(* Logix 5000 project; controller WuXi vendor 1 type 14 code 77 rev 20.12; software revision ? *)

TASK MainTask (continuous, watchdog 500 ms) : MainProgram

MODULES
   Controller : vendor 1 type 14 code 77 (CompactLogixL32EController 0, rev 20.12)
      LocalENB : 1769-L32E Ethernet Port (CompactLogixL32Ethernet 1, rev 20.11)
         inverter1 : vendor 1471 type 12 code 200 (Ethernet 192.168.1.205, rev 1.2, StandardDataDriven RPI 30 ms)
              inverter1:O.DATA[5]   // smart drive减速时间
              inverter1:O.DATA[0]   // smart drive输出控制字节
              inverter1:O.DATA[3]   // smart drive加速时间
              inverter1:O.DATA[1]   // smart drive频率
         inverter2 : vendor 1471 type 12 code 200 (Ethernet 192.168.1.206, rev 1.2, StandardDataDriven RPI 30 ms)
      Local : CompactBus (CompactVirtualAdapter 3, rev 20.11)
END_MODULES

TYPE SD_Control :   // Smart drive 控制数据
STRUCT
   MotorFW : BOOL;   // 电机正传
   MotorRVS : BOOL;   // 电机反转
   Reset : BOOL;   // 系统复位
   Output1 : BOOL;   // 输出1
   Output2 : BOOL;   // 输出2
   Output3 : BOOL;   // 输出3
   Output4 : BOOL;   // 输出4
   LocalEnable : BOOL;   // 转速,停止由smart drive内部控制
   Speed : INT;   // 运行速度 10000对应50HZ
   AccelerTime : INT;   // 加速时间
   DecelerTime : INT;   // 减速时间
END_STRUCT
END_TYPE

TYPE SD_State :   // smart drive状态数据
STRUCT
   Trip : BOOL;   // Trip bit位：0：正常，1：故障，触发条件是通过380V的开关进行触发产生
   WarningPresent : BOOL;   // Reserved
   RunningFWD : BOOL;   // 电机正向运行
   RunningRVS : BOOL;   // 电机反向运行
   Ready : BOOL;   // Ready bit位：0：故障，1：正常，触发条件系统各个子系统有异常就触发
   NetCtrlStat : BOOL;   // Reserved
   NetRefStats : BOOL;   // Reserved
   CurntFlow : BOOL;   // Reserved
   ReservedBit8 : BOOL;   // Reserved
   ReservedBit9 : BOOL;   // Reserved
   ReservedBit10 : BOOL;   // Reserved
   ReservedBit11 : BOOL;   // Reserved
   KeyPadOn : BOOL;   // Keypad On
   DiscOn : BOOL;   // Disconnecter On, 正常状态为ON(=1) 380V bit0相反
   ReservedBit14 : BOOL;   // Reserved
   ReservedBit15 : BOOL;   // Reserved
   ShortCircuit : BOOL;   // 短路
   OverLoad : BOOL;   // 过载
   PhaseLoss : BOOL;   // 缺相
   ReservedBit19 : BOOL;   // Reserved
   ReservedBit20 : BOOL;   // Reserved
   ControlPowerLost : BOOL;   // 控制电丢失
   ComFault : BOOL;   // 通讯错误
   ReservedBit23 : BOOL;   // Reserved
   PhaseImbalance : BOOL;   // 相位失衡
   ReservedBit25 : BOOL;   // Reserved
   ReservedBit26 : BOOL;   // Reserved
   ReservedBit27 : BOOL;   // Reserved
   ReservedBit28 : BOOL;   // Reserved
   HardwareFault : BOOL;   // 硬件故障
   ReservedBit30 : BOOL;   // Reserved
   ReservedBit31 : BOOL;   // Reserved
   Current : INT;   // 电流整数，需乘以0.01
   Input1 : BOOL;   // 输入1
   Input2 : BOOL;   // 输入2
   Input3 : BOOL;   // 输入3
   Input4 : BOOL;   // 输入4
   Input5 : BOOL;   // 输入5
   Input6 : BOOL;   // 输入6
   Input7 : BOOL;   // 输入7
   Input8 : BOOL;   // 输入8
END_STRUCT
END_TYPE

VAR_GLOBAL   (* controller tags *)
   ControlData1 : SD_Control;
   ControlData2 : SD_Control;
   CtlcycTest : BOOL;
   CtlForward1 : BOOL;   // 正传
   CtlForward2 : BOOL;
   CtlReset : BOOL;   // 复位
   CtlReverse1 : BOOL;   // 反转
   CtlReverse2 : BOOL;
   CtlStepTest : BOOL;   // 流程测试
   CtlStop : BOOL;
   CtlStop1 : BOOL;   // 停止
   CtlStop2 : BOOL;
   inverter1input1 : ALIAS FOR StateData1.Input1;
   inverter1input4 : ALIAS FOR StateData1.Input4;
   inverter2input1 : ALIAS FOR StateData2.Input1;
   inverter2input4 : ALIAS FOR StateData2.Input4;
   Left : BOOL;
   q11 : ALIAS FOR ControlData1.MotorFW;
   q12 : ALIAS FOR ControlData1.MotorRVS;
   q21 : ALIAS FOR ControlData2.MotorFW;
   q22 : ALIAS FOR ControlData2.MotorRVS;
   Right : BOOL;
   StateData1 : SD_State;
   StateData2 : SD_State;
END_VAR

PROGRAM MainProgram   (* main routine MainRoutine *)
VAR
   Action_000 : SFC_ACTION := (Status := 16#0020_0000, PauseTimer := 1);
   Action_001 : SFC_ACTION := (Status := 16#0020_0000, PauseTimer := 1, PRE := 2000);
   Action_002 : SFC_ACTION := (Status := 16#0020_0000, PauseTimer := 1);
   Action_003 : SFC_ACTION := (Status := 16#0020_0000, PauseTimer := 1, PRE := 2000);
   Step_000 : SFC_STEP := (Status := 16#0020_0000, PauseTimer := 1);
   Step_001 : SFC_STEP := (Status := 16#0020_0000, PauseTimer := 1);
   Step_002 : SFC_STEP := (Status := 16#0020_0000, PauseTimer := 1);
   Step_003 : SFC_STEP := (Status := 16#0020_0000, PauseTimer := 1);
   temp0 : BOOL;
   temp01 : BOOL;
   temp010 : BOOL;
   temp011 : BOOL;
   temp012 : BOOL;
   temp013 : BOOL;
   temp014 : BOOL;
   temp015 : BOOL;
   temp016 : BOOL;
   temp017 : BOOL;
   temp018 : BOOL;
   temp019 : BOOL;
   temp02 : BOOL;
   temp020 : BOOL;
   temp03 : BOOL;
   temp04 : BOOL;
   temp05 : BOOL;
   temp06 : BOOL;
   temp07 : BOOL;
   temp08 : BOOL;
   temp09 : BOOL;
   time0 : TIMER := (PRE := 70);   // 复位时间需保持>50ms
   time1 : TIMER;
   Tran_000 : BOOL;
   Tran_001 : BOOL;
   Tran_002 : BOOL;
   Tran_003 : BOOL;
END_VAR

ROUTINE cycTest   (* sequential function chart *)
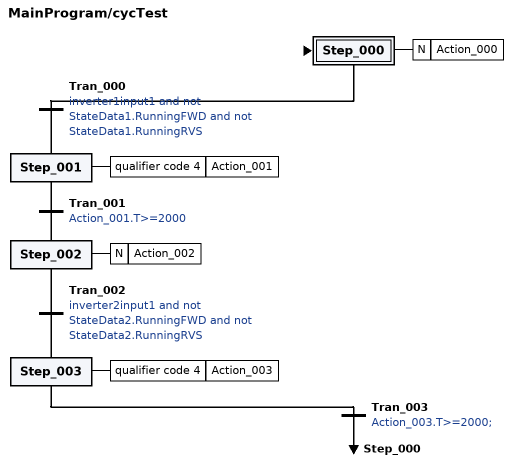
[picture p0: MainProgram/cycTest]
   INITIAL_STEP Step_000:
      ACTION Action_000 (N):
         Left:=1;
         
         
      END_ACTION
   END_STEP
   TRANSITION Tran_000 FROM Step_000 TO Step_001
      := inverter1input1 and not StateData1.RunningFWD and not StateData1.RunningRVS
         
   END_TRANSITION
   STEP Step_001:
      ACTION Action_001 (qualifier code 4):
         Left:=0;
      END_ACTION
   END_STEP
   TRANSITION Tran_001 FROM Step_001 TO Step_002
      := Action_001.T>=2000
   END_TRANSITION
   STEP Step_002:
      ACTION Action_002 (N):
         Right:=1;
      END_ACTION
   END_STEP
   TRANSITION Tran_002 FROM Step_002 TO Step_003
      := inverter2input1 and not StateData2.RunningFWD and not StateData2.RunningRVS
   END_TRANSITION
   STEP Step_003:
      ACTION Action_003 (qualifier code 4):
         Right:=0;
      END_ACTION
   END_STEP
   TRANSITION Tran_003 FROM Step_003 TO Step_000
      := Action_003.T>=2000;
         
   END_TRANSITION
END_ROUTINE

ROUTINE endcyc   (* structured text *)
   SFR(cycTest, Step_000);
   Left:=0;
   Right:=0;
   
END_ROUTINE

ROUTINE MainRoutine   (* ladder *)
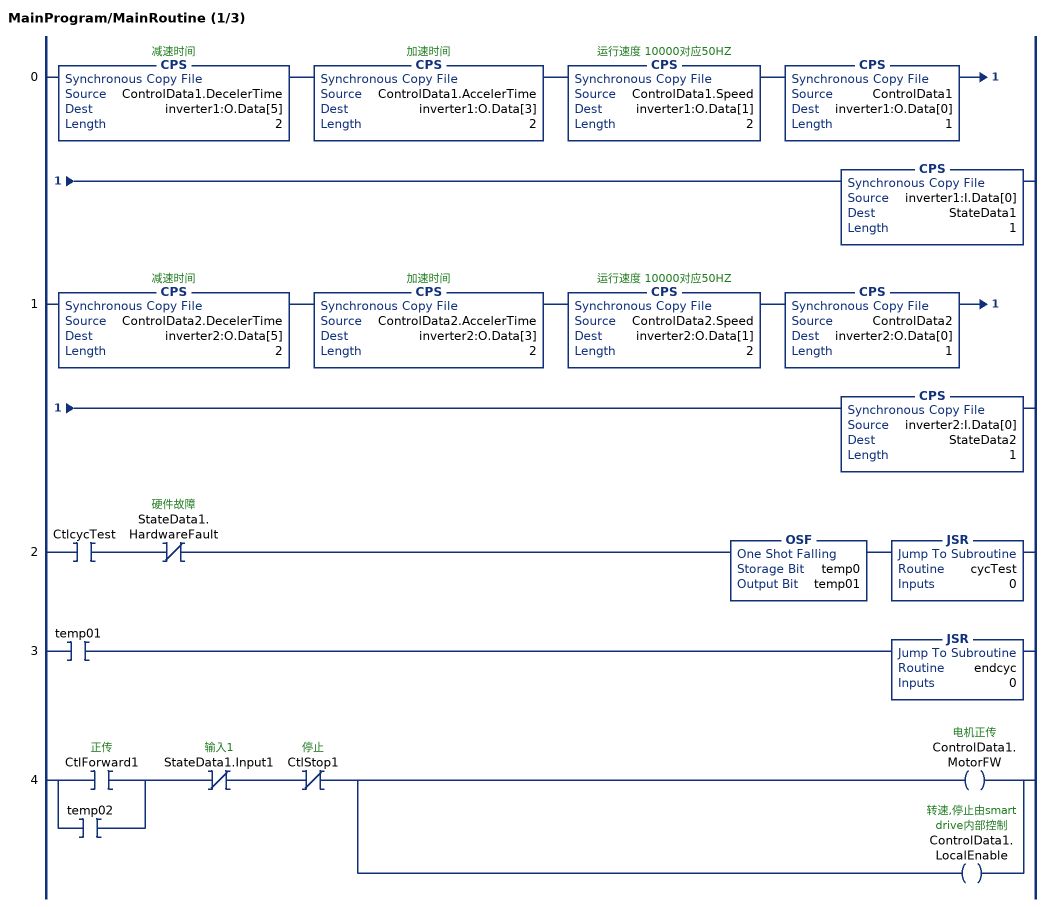
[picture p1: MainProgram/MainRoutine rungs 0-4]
   0: CPS(ControlData1.DecelerTime,inverter1:O.Data[5],2)CPS(ControlData1.AccelerTime,inverter1:O.Data[3],2)CPS(ControlData1.Speed,inverter1:O.Data[1],2)CPS(ControlData1,inverter1:O.Data[0],1)CPS(inverter1:I.Data[0],StateData1,1);
   1: CPS(ControlData2.DecelerTime,inverter2:O.Data[5],2)CPS(ControlData2.AccelerTime,inverter2:O.Data[3],2)CPS(ControlData2.Speed,inverter2:O.Data[1],2)CPS(ControlData2,inverter2:O.Data[0],1)CPS(inverter2:I.Data[0],StateData2,1);
   2: XIC(CtlcycTest)XIO(StateData1.HardwareFault)OSF(temp0,temp01)JSR(cycTest,0);
   3: XIC(temp01)JSR(endcyc,0);
   4: [XIC(CtlForward1) ,XIC(temp02) ]XIO(StateData1.Input1)XIO(CtlStop1)[OTE(ControlData1.MotorFW) ,OTE(ControlData1.LocalEnable) ];
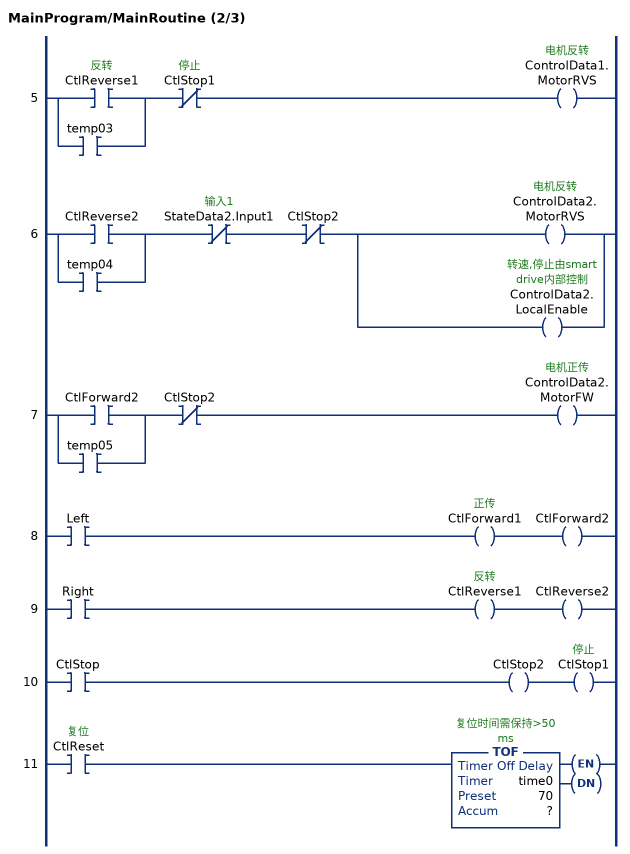
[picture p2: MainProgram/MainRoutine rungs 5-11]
   5: [XIC(CtlReverse1) ,XIC(temp03) ]XIO(CtlStop1)OTE(ControlData1.MotorRVS);
   6: [XIC(CtlReverse2) ,XIC(temp04) ]XIO(StateData2.Input1)XIO(CtlStop2)[OTE(ControlData2.MotorRVS) ,OTE(ControlData2.LocalEnable) ];
   7: [XIC(CtlForward2) ,XIC(temp05) ]XIO(CtlStop2)OTE(ControlData2.MotorFW);
   8: XIC(Left)OTE(CtlForward1)OTE(CtlForward2);
   9: XIC(Right)OTE(CtlReverse1)OTE(CtlReverse2);
   10: XIC(CtlStop)OTE(CtlStop2)OTE(CtlStop1);
   11: XIC(CtlReset)TOF(time0,?,?);
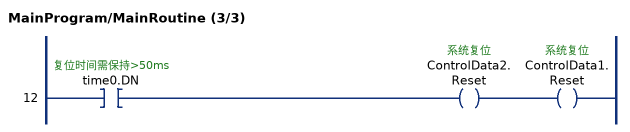
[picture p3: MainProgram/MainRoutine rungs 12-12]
   12: XIC(time0.DN)OTE(ControlData2.Reset)OTE(ControlData1.Reset);
END_ROUTINE
END_PROGRAM
